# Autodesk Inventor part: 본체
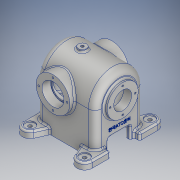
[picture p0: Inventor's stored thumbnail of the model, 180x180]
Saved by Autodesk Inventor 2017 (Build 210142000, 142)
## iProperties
Part Number: 본체
Material: 알루미늄 6061
Document SubType Name: Modeling
Designer: MRC
Density: 2.7 g/cm^3
Appearance: 알루미늄 - 평지
Mass: 1388.29 g
Surface Area: 1150.5 cm^2
Volume: 514.181 cm^3
Author: MRC
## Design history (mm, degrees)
sketch "스케치3"
  geometry: L1 (45, 0)-(45, -76); L2 (45, -76)-(-45, -76); L3 (-45, -76)-(-45, 0); A1 r 45 centre (0, 0) between (45, 0) and (-45, 0); 1 further point
  constraints: 6 end point, 2 point on circle, 1 centre point, 1 coincident, 1 parallel, 1 perpendicular, 1 tangent, 1 vertical
  dimensions: "d6" = 90 diameter of A1; "d13" = 76 distance of L1.start L1.end; "d14" = 76 distance of L2.end L3.end
extrude "돌출2" new body sketch "스케치3" stored distance "d15" = 108; taper "d16" = 0 deg
sketch "스케치5"
  geometry: C1 r 28.5 at (0, 0); 1 further point
  constraints: 1 centre point, 1 coincident
  dimensions: "d23" = 57 diameter of C1
extrude "돌출3" join sketch "스케치5" distance "d24" = 6; taper "d25" = 0 deg
sketch "스케치7"
  geometry: L1 (28.5, 60)-(-28.5, 60) reference; L2 (0, 60)-(0, -14); L3 (0, -54)-(0, 54) reference; C1 r 31 at (0, -14); 1 further point
  constraints: 2 end point, 1 centre point, 1 coincident, 1 midpoint, 1 point on line
  dimensions: "d29" = 74 distance of L2.start L2.end; "d30" = 62 diameter of C1
extrude "돌출5" join sketch "스케치7" stored distance "d31" = 108; taper "d32" = 0 deg
sketch "스케치8"
  geometry: L1 (0, -14)-(49, -14); C1 r 31 at (0, -14) reference; 1 further point
  constraints: 2 end point, 1 horizontal
  dimensions: "d33" = 49 distance of L1.start L1.end
node "작업 평면1"
sketch "스케치9"
  geometry: C1 r 7.5 at (0, 0); 2 further points
  constraints: 1 centre point, 1 coincident
  dimensions: "d35" = 15 diameter of C1
extrude "돌출6" join sketch "스케치9" distance "d36" = 28; taper "d37" = 0 deg
node "작업 평면2"
sketch "스케치11"
  geometry: L1 (45, 0)-(-45, 0); A1 r 45 centre (0, 0) between (45, 0) and (-45, 0) reference; A2 r 45 centre (0, 0) between (45, 0) and (-45, 0) reference; A3 r 45 centre (0, 0) between (-45, 0) and (45, 0); 1 further point
  constraints: 2 end point, 2 point on circle, 1 centre point, 1 coincident, 1 horizontal
sketch "스케치14"
  geometry: L1 (-45, -76)-(-45, 0) reference; L2 (45, 0)-(45, -76) reference; L3 (-36, -76)-(-36, -27); L4 (36, -27)-(36, -76); L5 (-36, -76)-(36, -76); L6 (45, -76)-(-45, -76) reference; A1 r 45 centre (0, 0) between (-45, 0) and (45, 0) reference; 1 further point
  constraints: 6 end point, 2 parallel, 2 point on circle, 1 collinear
  dimensions: "d57" = 9 distance between parallel lines of L1 L3; "d58" = 9 distance between parallel lines of L2 L4
extrude "돌출9" cut sketch "스케치14" stored distance "d59" = 90; taper "d60" = 0 deg
sketch "스케치15"
  geometry: C1 r 17.5 at (0, 0); C2 r 31 at (0, 0) reference
  constraints: 1 centre point, 1 coincident
  dimensions: "d62" = 35 diameter of C1
extrude "돌출10" cut sketch "스케치15" distance "d63" = 146; taper "d64" = 0 deg
sketch "스케치16"
  geometry: C1 r 20 at (0, 0); C2 r 17.5 at (0, 0) reference; 1 further point
  constraints: 1 centre point, 1 coincident
  dimensions: "d65" = 40 diameter of C1
extrude "돌출11" cut sketch "스케치16" distance "d66" = 16; taper "d67" = 0 deg
sketch "스케치17"
  geometry: C1 r 16.5 at (0, 0); 1 further point
  constraints: 1 centre point, 1 coincident
  dimensions: "d68" = 33 diameter of C1
extrude "돌출12" cut sketch "스케치17" distance "d69" = 101.5; taper "d70" = 0 deg
sketch "스케치18"
  geometry: L1 (0, -45)-(0, -54) reference; L2 (0, -54)-(0, -45); L3 (0, -45)-(36, -45); L4 (36, -45)-(36, 45); L5 (36, 45)-(0, 45); L6 (0, 54)-(0, 17) reference; L7 (45, 54)-(0, 54) reference; L8 (0, -54)-(45, -54) reference; L9 (-16.5, 60)-(16.5, 60) reference; L10 (0, -45)-(0, 45); L11 (0, 45)-(0, 60); 1 further point
  constraints: 12 end point, 7 perpendicular, 3 vertical, 1 midpoint, 1 point on line
  dimensions: "d73" = 72 diameter of L4 L2; "d77" = 9 distance between parallel lines of L5 L7; "d78" = 9 distance between parallel lines of L8 L3
revolve "회전2" sketch "스케치18" stored, may be unused: angle "d80" = 90 deg
sketch "스케치19"
  geometry: L1 (9, -99)-(9, -9) reference; L2 (9, -99)-(81, -99) reference; L3 (81, -9)-(81, -99) reference; L4 (81, -9)-(9, -9) reference; L5 (0, -108)-(0, 0) reference; L6 (90, -108)-(0, -108) reference; L7 (-20.693, -91.21)-(0, -82); L8 (0, -108)-(0, -99) reference; L9 (0, -82)-(0, -108); L10 (0, -108)-(18, -108); L11 (0, -108)-(90, -108) reference; L12 (18, -108)-(18, -118); L13 (18, -118)-(-15, -118); A1 r 14 centre (-15, -104) between (-20.693, -91.21) and (-15, -118); 1 further point
  constraints: 10 end point, 2 point on circle, 2 point on line, 2 tangent, 1 centre point, 1 collinear, 1 vertical
  dimensions: "d81" = 60 horizontal distance of point (45, -54) A1.centre; "d82" = 50 vertical distance of point (45, -54) A1.centre; "d83" = 28 diameter of A1; "d85" = 18 distance between parallel lines of L5 L12; "d86" = 33 distance of L12.end L13.end; "d87" = 20.69259 horizontal distance of L7.start L7.end
extrude "돌출13" join sketch "스케치19" distance "d88" = 12; taper "d89" = 0 deg
sketch "스케치20"
  geometry: A1 r 14 centre (-15, 104) between (-15, 118) and (-20.693, 91.21) reference; 2 further points
  constraints: 1 coincident
hole "구멍1" sketch "스케치20" at (-15, 104) diameter "d90" = 6.6; stored, may be unused: countersink angle "d94" = 90 deg, drill point angle "d96" = 0 deg; dims "d91" = 6, "d92" = 18, "d93" = 2, "d95" = 12
sketch "스케치22"
  geometry: A1 r 26 centre (0, 0) between (0, 26) and (26, 0); 3 further points
  constraints: 4 point on circle, 2 horizontal alignment, 2 vertical alignment, 1 centre point, 1 coincident
  dimensions: "d100" = 52 diameter of A1
hole "구멍2" sketch "스케치22" at (0, 26), (26, 0), (0, -26), (-26, 0) diameter "d101" = 3.242; stored, may be unused: countersink angle "d105" = 90 deg, drill point angle "d107" = 118 deg; dims "d102" = 8, "d103" = 19.05, "d104" = 4.775, "d106" = 10
sketch "스케치23"
  geometry: A1 r 23 centre (0, 0) between (0, 23) and (23, 0); 3 further points
  constraints: 4 point on circle, 2 horizontal alignment, 2 vertical alignment, 1 centre point, 1 coincident
  dimensions: "d108" = 46 diameter of A1
hole "구멍3" sketch "스케치23" at (0, 23), (23, 0), (-23, 0), (0, -23) diameter "d109" = 3.242; stored, may be unused: countersink angle "d113" = 90 deg, drill point angle "d115" = 118 deg; dims "d110" = 8, "d111" = 19.05, "d112" = 4.775, "d114" = 10
sketch "스케치24"
  geometry: 2 further points
  constraints: 1 other
hole "구멍4" sketch "스케치24" at (0, 0) diameter "d116" = 5.188; stored, may be unused: countersink angle "d120" = 90 deg, drill point angle "d122" = 118 deg; dims "d117" = 16, "d118" = 19.05, "d119" = 4.775, "d121" = 16
fillet "모깎기1" dims "d123" = 0.3
fillet "모깎기2" dims "d124" = 3
fillet "모깎기4" dims "d126" = 3
sketch "스케치25"
  geometry: L1 (-36, -76)-(36, -76) reference; L2 (-20, -76)-(20, -76); L3 (20, -76)-(20, -53); L4 (20, -53)-(-20, -53); L5 (-20, -53)-(-20, -76); 1 further point
  constraints: 8 end point, 2 parallel, 1 horizontal, 1 perpendicular, 1 point on line
  dimensions: "d127" = 20 distance from line of point (0, 0) L5; "d128" = 40 distance of L3.end L4.end; "d129" = 23 distance between parallel lines of L1 L4
extrude "돌출14" cut sketch "스케치25" stored distance "d130" = 156.75; taper "d131" = 0 deg
fillet "모깎기6" dims "d133" = 3
fillet "모깎기7" dims "d134" = 3
fillet "모깎기8" dims "d135" = 3
fillet "모깎기9" dims "d136" = 12
fillet "모깎기10" dims "d137" = 3
sketch "스케치26"
  geometry: L1 (60, -76)-(30, -76) reference; 2 further points
  constraints: 1 vertical alignment, 1 other
  dimensions: "d138" = 35 distance from line of L1 point (0, -41)
feature "엠보싱1" sketch "스케치26" dims "d139" = 0.5, "d140" = 0
sketch "스케치27"
  geometry: L1 (49, -6.5)-(49, -21.5) reference; L2 (49, -14)-(-49, -14); 1 further point
  constraints: 2 end point, 1 horizontal, 1 midpoint
  dimensions: "d141" = 98 distance of L2.start L2.end
node "작업 평면3"
sketch "스케치29"
  geometry: C1 r 7.5 at (0, 0) reference; C2 r 2.594 at (0, 0) reference; C3 r 7.5 at (0, 0); C4 r 2.594 at (0, 0); 1 further point
  constraints: 2 centre point, 2 coincident, 2 concentric
extrude "돌출16" join sketch "스케치29" stored distance "d146" = 10; taper "d147" = 0 deg
sketch "스케치30"
  geometry: 2 further points
  constraints: 1 other
hole "구멍5" sketch "스케치30" at (0, 0) diameter "d148" = 5.188; stored, may be unused: countersink angle "d152" = 90 deg, drill point angle "d154" = 118 deg; dims "d149" = 16, "d150" = 4, "d151" = 2, "d153" = 16
fillet "모깎기12" dims "d155" = 3
fillet "모깎기13" dims "d156" = 3
node "솔리드2"
mirror "미러1"
mirror "미러2"
mirror "미러3"
node "투영된 루프1"
other parameters: "d43" = -12
